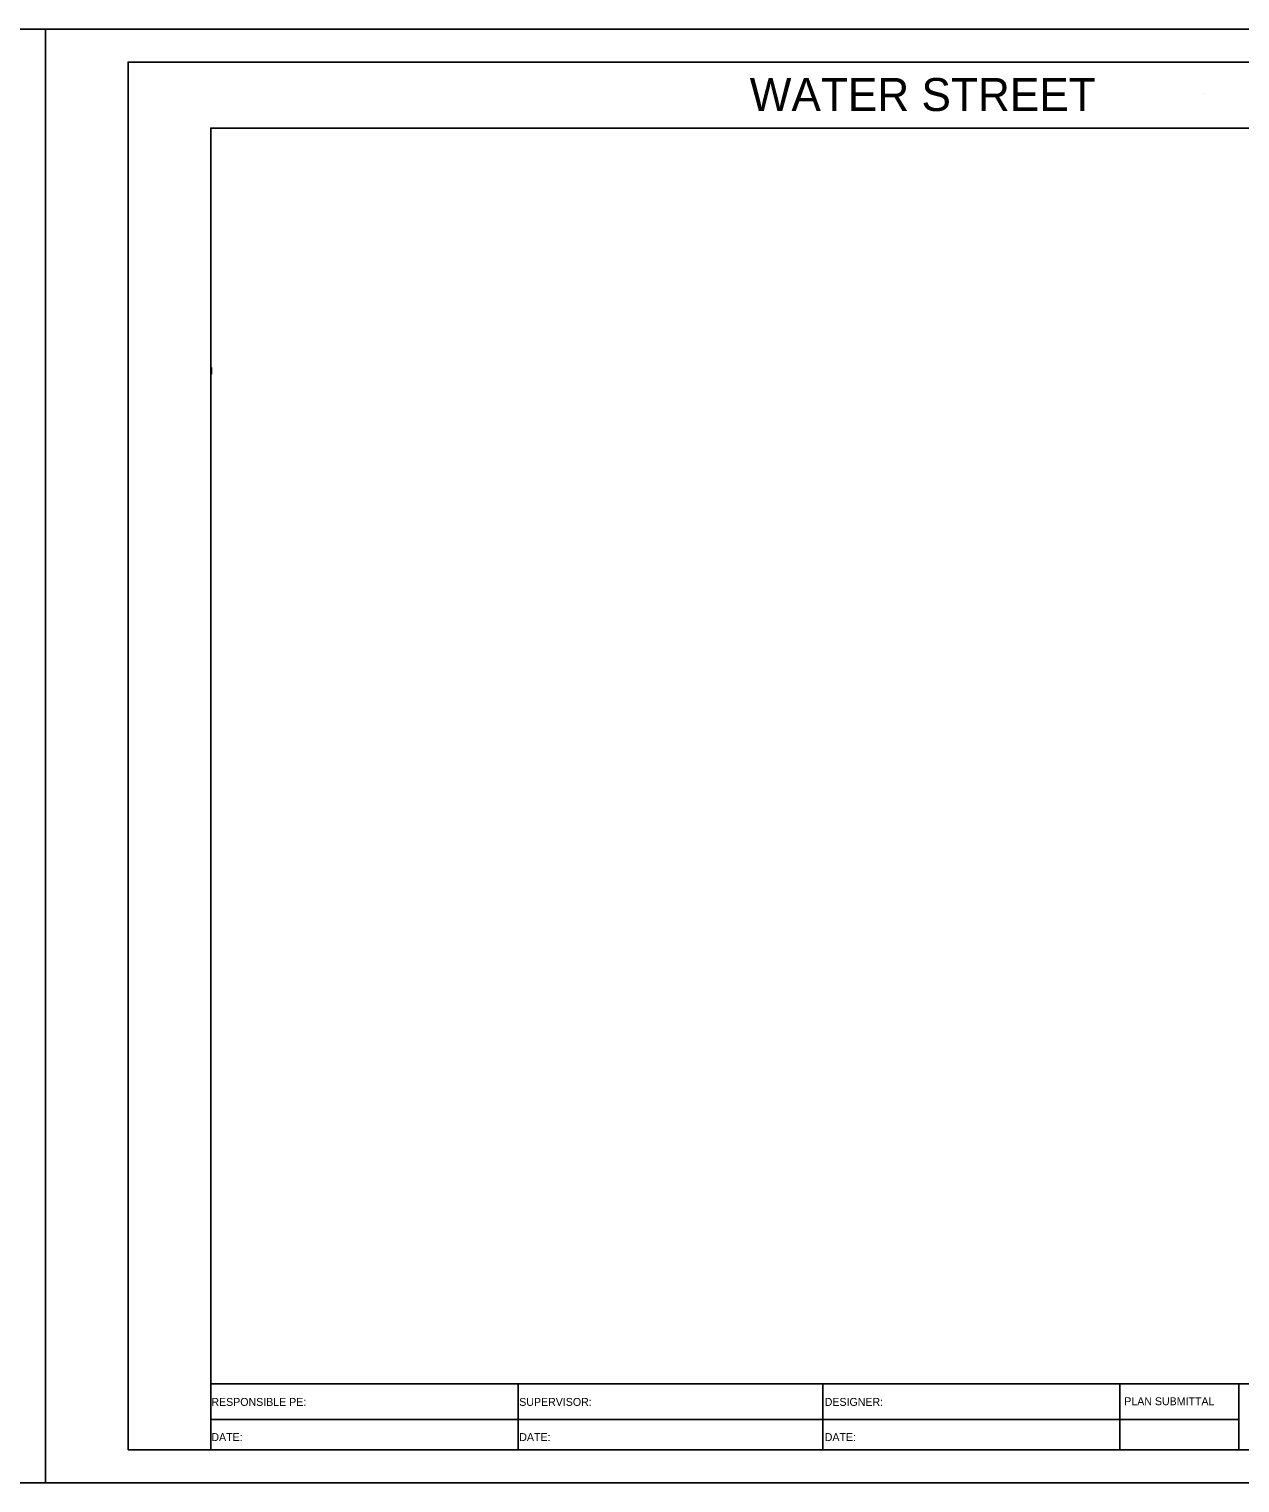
# Model space of a CAD drawing. Extents: x 1797478 to 1808916, y 246529 to 250952.
# Drawn here: x 1803813.5 to 1803996.8, y 250064.4 to 250284.4 of the extents above; entities that cross this region are included whole.
import ezdxf

# ---------------------------------------------------------------- set-up
doc = ezdxf.new("R2010")
doc.units = 0
for name, color, linetype in [('2', 7, 'Continuous'), ('ANNO-SHT', 7, 'Continuous'), ('ANNO-TXT', 7, 'Continuous'), ('AXIS', 7, 'Continuous'), ('DRAINAGE', 7, 'Continuous'), ('Level 1', 7, 'Continuous'), ('Level 62', 7, 'Continuous'), ('SHT-BDR', 7, 'Continuous'), ('SHT-BNDRY', 7, 'Continuous')]:
    doc.layers.add(name, color=color, linetype=linetype)

# ---------------------------------------------------------------- blocks, each defined once
blk = doc.blocks.new('SC47208')
at = {"layer": 'Level 1'}
blk.add_line((0, 0), (0, 0), dxfattribs=at)

msp = doc.modelspace()

# ---------------------------------------------------------------- linework, layer by layer
at = {"layer": '2'}
msp.add_lwpolyline([(1803841.12, 250233.21), (1803841.1, 250232.21)], dxfattribs=at)
msp.add_lwpolyline([(1803841.12, 250233.21), (1803841.1, 250232.21)], dxfattribs=at)
at = {"layer": 'AXIS'}
msp.add_line((1803841, 250189.42), (1803841, 250189.43), dxfattribs=at)
at = {"layer": 'Level 62'}
for points in [[(1803476, 250064.42), (1803816, 250064.42), (1803816, 250284.42), (1803476, 250284.42)], [(1803816, 250064.42), (1804156, 250064.42), (1804156, 250284.42), (1803816, 250284.42)]]:
    msp.add_lwpolyline(points, close=True, dxfattribs=at)
at = {"layer": 'SHT-BDR'}
msp.add_lwpolyline([(1803841, 250079.43), (1804141, 250079.43), (1804141, 250269.43), (1803841, 250269.43)], close=True, dxfattribs=at)
at = {"layer": 'SHT-BNDRY'}
for p, q in [((1803841, 250069.42), (1803841, 250079.43)), ((1803887.52, 250079.43), (1803887.52, 250069.42)), ((1803933.67, 250069.42), (1803933.67, 250079.43)), ((1803978.59, 250069.42), (1803978.59, 250079.43)), ((1803996.63, 250069.42), (1803996.63, 250079.43)), ((1803841, 250074.03), (1803996.63, 250074.03))]:
    msp.add_line(p, q, dxfattribs=at)
msp.add_lwpolyline([(1803828.5, 250069.42), (1804151, 250069.42), (1804151, 250279.42), (1803828.5, 250279.42)], close=True, dxfattribs=at)

# ---------------------------------------------------------------- block references
at = {"layer": 'DRAINAGE', "xscale": 0.2, "yscale": 0.20000000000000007, "rotation": -116.41666666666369}
msp.add_blockref('SC47208', (1803991.32, 250274.62), dxfattribs=at)
msp.add_blockref('SC47208', (1803991.32, 250274.62), dxfattribs=at)

# ---------------------------------------------------------------- texts
at = {"layer": 'ANNO-SHT'}
msp.add_text('         WATER STREET         ', height=4.9995, rotation=360, dxfattribs=at).set_placement((1803905.87, 250272.02))
at = {"layer": 'ANNO-TXT'}
for s, p in [('RESPONSIBLE PE:', (1803841.1, 250076.08)), ('SUPERVISOR:', (1803887.7, 250076.08)), ('DESIGNER:', (1803933.94, 250076.08)), ('PLAN SUBMITTAL', (1803979.28, 250076.18)), ('DATE:', (1803841.1, 250070.76)), ('DATE:', (1803887.7, 250070.76)), ('DATE:', (1803933.94, 250070.76))]:
    msp.add_text(s, height=1.2, rotation=360, dxfattribs=at).set_placement(p)

doc.saveas('drawing.dxf')
